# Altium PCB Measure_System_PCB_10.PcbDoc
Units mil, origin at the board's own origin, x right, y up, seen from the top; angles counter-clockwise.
Board outline 6000 x 4000 mil, 2 copper layers (Top Layer, Bottom Layer); 44 components, 29 nets, 115 pads, 0 vias.
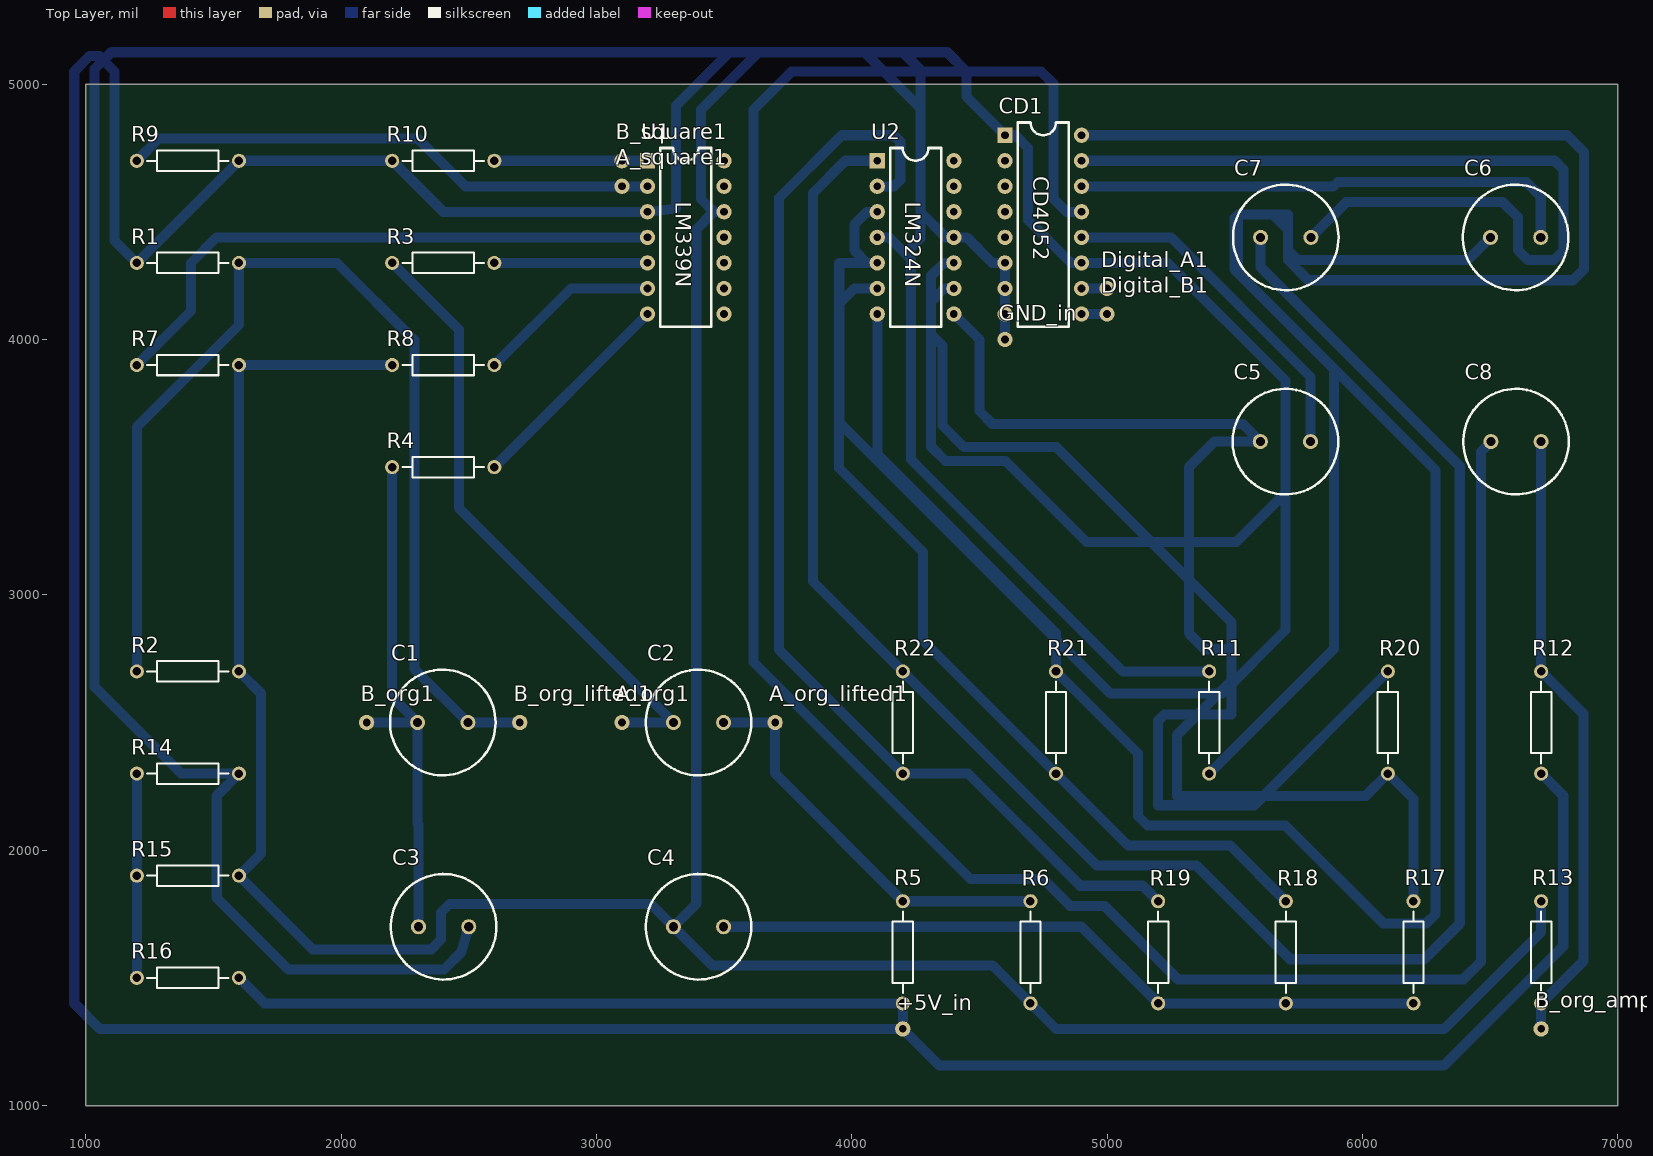
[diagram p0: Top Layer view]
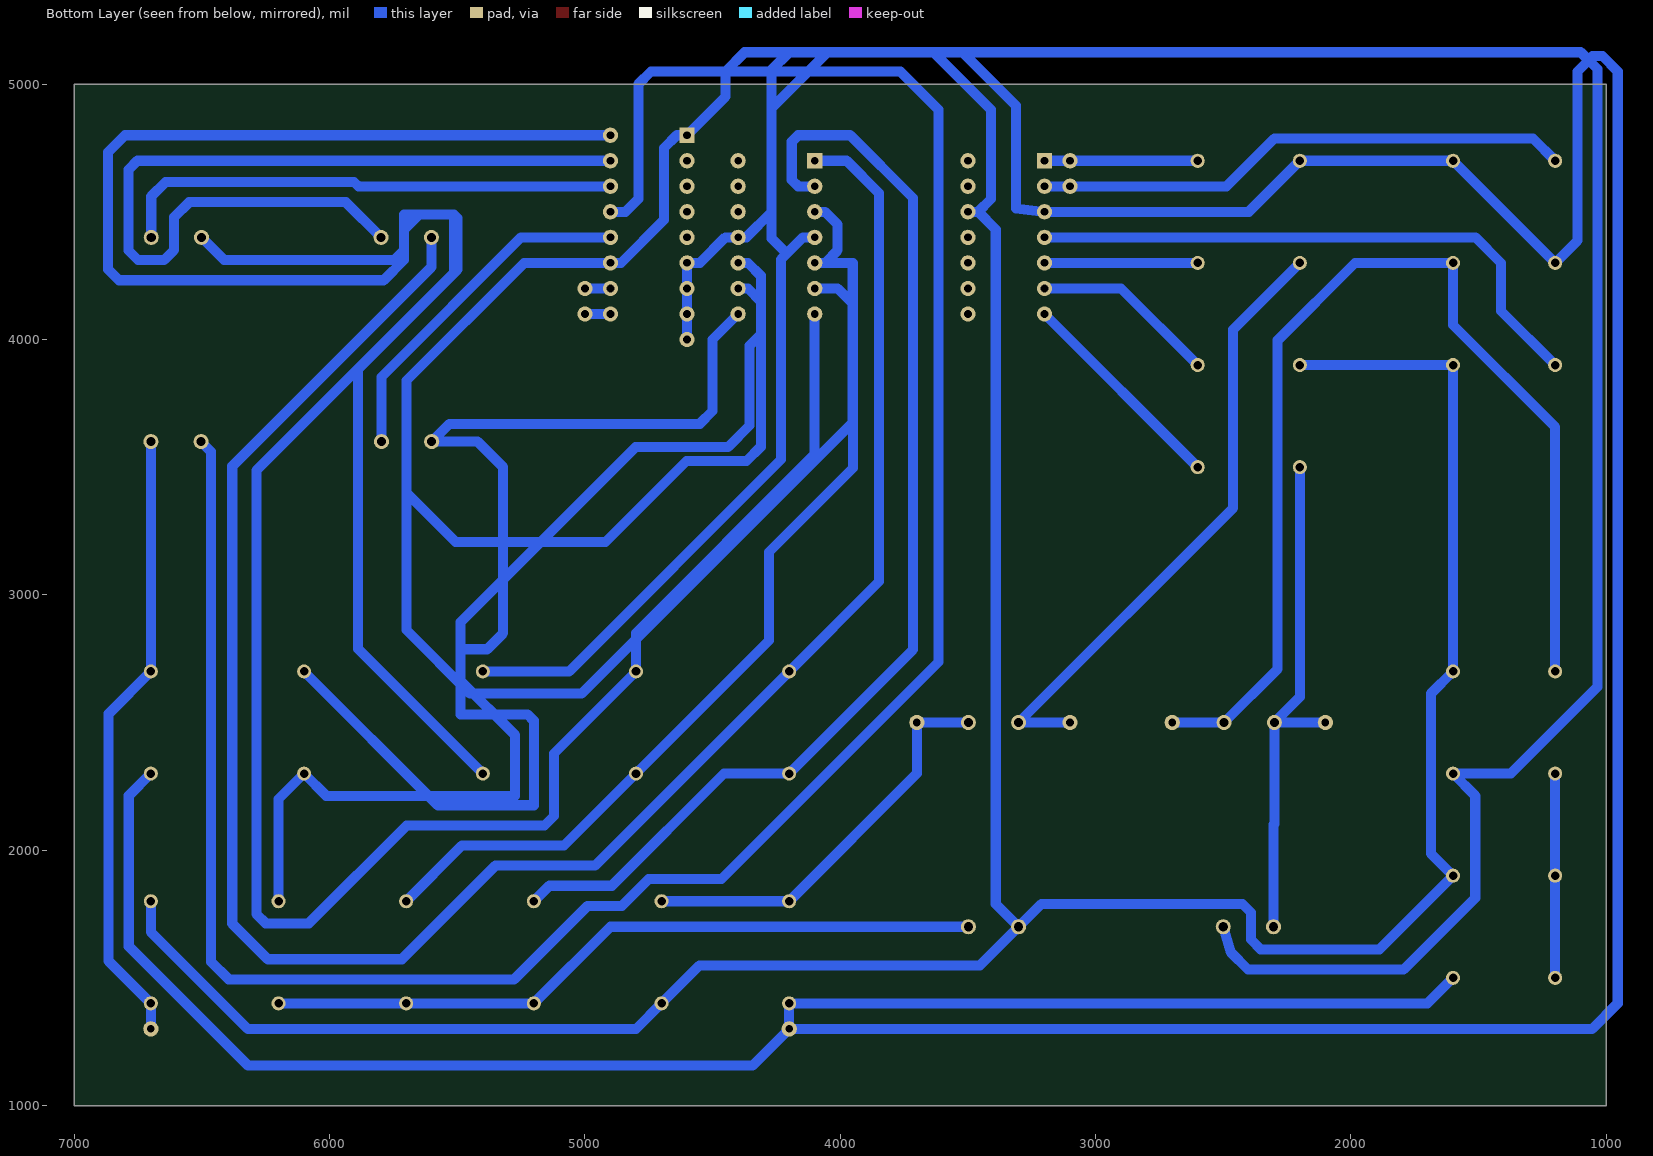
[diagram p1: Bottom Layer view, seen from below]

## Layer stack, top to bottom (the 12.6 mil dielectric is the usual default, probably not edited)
Top Solder: solder mask 0.4, Solder Resist, Dk 3.5
Top Layer: signal copper 1.4
Dielectric 1: dielectric 12.6, FR-4, Dk 4.8
Bottom Layer: signal copper 1.4
Bottom Solder: solder mask 0.4, Solder Resist, Dk 3.5

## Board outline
1000,1000 7000,1000 7000,5000 1000,5000

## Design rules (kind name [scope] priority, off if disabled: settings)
Clearance [All] p1: gap=39.37 ignorepadtopadclearanceinfootprint=FALSE
PolygonConnect [All] p1: connectstyle=Relief reliefconductorwidth=10 reliefentries=4 polygonreliefangle="90 Angle" airgapwidth=10
RoutingLayers [All] p1: top layer_v5=FALSE bottom layer_v5=TRUE
RoutingVias [All] p1: holewidth=28 width=50 viastyle="Through Hole" minholewidth=28 minwidth=50 maxholewidth=28 maxwidth=50
SolderMaskExpansion [All] p1: expansion=4 istentingtop=FALSE
Width [All] p1: maxlimit=3937.01 minlimit=19.68 preferedwidth=39.37 minimp=50.000000 maximp=50.000000 favimp=50.000000
29 further rules are at their usual default settings.

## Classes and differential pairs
component class Part_Square: C1 C2 R1 R2 R3 R4 R5 R6 R7 R8 R9 R10 U1
component class Part_PGA: C3 C4 C5 C6 C7 C8 CD1 R11 R12 R13 R14 R15 R16 R17 R18 R19 R20 R21 R22 U2
component class Measure_System_Main: +5V_in A_org1 A_org_lifted1 A_square1 B_org1 B_org_amped_lifted1 B_org_lifted1 B_square1 Digital_A1 Digital_B1 GND_in

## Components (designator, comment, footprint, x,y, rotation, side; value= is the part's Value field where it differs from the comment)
+5V_in "Hole" Hole 4200,1300 r90 top
A_org1 "Hole" Hole 3100,2500 r90 top
A_org_lifted1 "Hole" Hole 3700,2500 r90 top
A_square1 "Hole" Hole 3100,4600 r90 top
B_org1 "Hole" Hole 2100,2500 r90 top
B_org_amped_lifted1 "Hole" Hole 6700,1300 r90 top
B_org_lifted1 "Hole" Hole 2700,2500 r90 top
B_square1 "Hole" Hole 3100,4700 r90 top
C1 "Cap Pol1" RB5-10.5 2398.43,2500 r0 top value=10u
C2 "Cap Pol1" RB5-10.5 3400,2500 r0 top value=10u
C3 "Cap Pol1" RB5-10.5 2401.57,1700 r0 top value=10u
C4 "Cap Pol1" RB5-10.5 3400,1700 r0 top value=10u
C5 "Cap Pol1" RB5-10.5 5698.43,3600 r0 top value=10u
C6 "Cap Pol1" RB5-10.5 6600,4400 r0 top value=10u
C7 "Cap Pol1" RB5-10.5 5700,4400 r0 top value=10u
C8 "Cap Pol1" RB5-10.5 6601.57,3600 r0 top value=10u
CD1 "CD4052" CD4052 4600,4800 r0 top
Digital_A1 "Hole" Hole 5000,4200 r90 top
Digital_B1 "Hole" Hole 5000,4100 r90 top
GND_in "Hole" Hole 4600,4000 r90 top
R1 "Res2" AXIAL-0.4 1400,4300 r180 top value=100k
R2 "Res2" AXIAL-0.4 1400,2700 r180 top value=100k
R3 "Res2" AXIAL-0.4 2400,4300 r180 top value=1k
R4 "Res2" AXIAL-0.4 2400,3500 r180 top value=1k
R5 "Res2" AXIAL-0.4 4200,1600 r270 top value=100k
R6 "Res2" AXIAL-0.4 4700,1600 r90 top value=100k
R7 "Res2" AXIAL-0.4 1400,3900 r180 top value=10k
R8 "Res2" AXIAL-0.4 2400,3900 r180 top value=10k
R9 "Res2" AXIAL-0.4 1400,4700 r180 top value=10k
R10 "Res2" AXIAL-0.4 2400,4700 r180 top value=10k
R11 "Res2" AXIAL-0.4 5400,2500 r90 top value=200
R12 "Res2" AXIAL-0.4 6700,2500 r270 top value=100k
R13 "Res2" AXIAL-0.4 6700,1600 r270 top value=100k
R14 "Res2" AXIAL-0.4 1400,2300 r0 top value=100k
R15 "Res2" AXIAL-0.4 1400,1900 r180 top value=100k
R16 "Res2" AXIAL-0.4 1400,1500 r180 top value=100k
R17 "Res2" AXIAL-0.4 6200,1600 r90 top value=50k
R18 "Res2" AXIAL-0.4 5700,1600 r90 top value=24k
R19 "Res2" AXIAL-0.4 5200,1600 r90 top value=12k
R20 "Res2" AXIAL-0.4 6100,2500 r90 top value=100k
R21 "Res2" AXIAL-0.4 4800,2500 r90 top value=100k
R22 "Res2" AXIAL-0.4 4200,2500 r90 top value=100k
U1 "LM339N" LM339N 3200,4700 r0 top
U2 "LM324N" LM324N 4100,4700 r0 top

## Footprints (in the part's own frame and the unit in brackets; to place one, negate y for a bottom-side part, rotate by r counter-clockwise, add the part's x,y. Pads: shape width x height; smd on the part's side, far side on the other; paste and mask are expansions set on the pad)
AXIAL-0.4 [mm] "Axial Device, Thru-Hole; 2 Leads; 0.4 in Pin Spacing"
  round 1.4 hole 0.85: 1(-5.08,0) 2(5.08,0)
  silkscreen extent -4.06,-1.02 4.06,1.02
CD4052 [mil]
  rect 60x60 hole 30: 1(0,0)
  round 60 hole 30 mask+4: 2(0,-100) 3(0,-200) 4(0,-300) 5(0,-400) 6(0,-500) 7(0,-600) 8(0,-700) 9(300,-700) 10(300,-600) 11(300,-500) 12(300,-400) 13(300,-300) 14(300,-200) 15(300,-100) 16(300,0)
  silkscreen extent 50,-750 250,50
Hole [mil]
  round 60 hole 30 mask+4: 1(0,0)
LM324N [mil]
  rect 60x60 hole 30: 1(0,0)
  round 60 hole 30 mask+4: 2(0,-100) 3(0,-200) 4(0,-300) 5(0,-400) 6(0,-500) 7(0,-600) 8(300,-600) 9(300,-500) 10(300,-400) 11(300,-300) 12(300,-200) 13(300,-100) 14(300,0)
  silkscreen extent 50,-650 250,50
LM339N [mil]
  rect 60x60 hole 30: 1(0,0)
  round 60 hole 30 mask+4: 2(0,-100) 3(0,-200) 4(0,-300) 5(0,-400) 6(0,-500) 7(0,-600) 8(300,-600) 9(300,-500) 10(300,-400) 11(300,-300) 12(300,-200) 13(300,-100) 14(300,0)
  silkscreen extent 50,-650 250,50
RB5-10.5 [mm] "Capacitor (Radial); 2 Leads"
  round 1.5 hole 0.9: 1(-2.5,0) 2(2.5,0)
  silkscreen extent -5.25,-5.25 5.25,5.25

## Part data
C1 C2 C3 C4 C5 C6 C7 C8: "Polarized Capacitor (Radial)"
R1 R2 R3 R4 R5 R6 R7 R8 R9 R10 R11 R12 R13 R14 R15 R16 R17 R18 R19 R20 R21 R22: "Resistor"

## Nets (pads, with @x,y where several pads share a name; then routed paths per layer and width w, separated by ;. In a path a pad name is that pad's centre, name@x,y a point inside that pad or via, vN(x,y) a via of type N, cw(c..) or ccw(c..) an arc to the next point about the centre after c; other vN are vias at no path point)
+5: +5V_in.1 R1.2 R5.2 R9.1 R10.2 R11.2 R12.2 R16.1 U1.3 U2.4 | length 21267.8
  Bottom Layer w39.37: R16.1 1700,1400 R5.2 +5V_in.1 ; U2.4 4103.76,4400 4146,4400 4209.38,4336.62 ; R11.2 5061.82,2700 4232,3529.82 4232,4314 4209.38,4336.62 ; R12.2 6786.62,2213.38 6786.62,1623.62 6319,1156 4344,1156 +5V_in.1 ; +5V_in.1 1055,1300 955,1400 955,5050 1015,5110 1053,5110 1113,5050 1113,4387 R1.2 R9.1 R10.2 2400,4500 U1.3 3312,4513 3312,4916 3521,5125 4200,5125 4269,5056 4269,4396.24 4209.38,4336.62
B_org: B_org1.1 C1.1 C3.1 R4.2 | length 2042.7
  Bottom Layer w39.37: B_org1.1 C1.1 ; R4.2 2200,2600 C1.1 ; C3.1 2303.15,2100 2300,2103.15 C1.1
B_org_amp_1: C3.2 CD1.1 CD1.11 R14.2 U2.3 U2.5 U2.10 | length 17680.3
  Bottom Layer w39.37: C3.2 2470.48,1600 2403.15,1532.67 1793.33,1532.67 1513,1813 1513,2213 R14.2 1374,2300 1034,2640 1034,5059 1100,5125 4374,5125 4449,5050 4449,4951 CD1.1 4640,4800 4690,4750 4690,4469 4859,4300 CD1.11 5238,4300 ; U2.5 4060,4300 ; U2.3 4060,4500 4010,4450 4010,4350 4060,4300 ; U2.10 4360.94,4300 4310.94,4250 4310.94,3580 4366.94,3524 4602,3524 4919,3207 5506,3207 5699,3400 ; 4060,4300 3951,4300 3951,3675 5013,2613 5450,2613 5699,2862 5699,3400 ; 5238,4300 5238.64,4300 5699,3839.64 5699,3839 ; 5238,4300 5699,3839 ; 5699,3400 5699,3839
B_org_amp_2.5: C5.2 CD1.12 | length 1376.5
  Bottom Layer w39.37: CD1.12 5250,4400 5796.85,3853.15 C5.2
B_org_amp_5: C6.2 CD1.14 | length 1989.5
  Bottom Layer w39.37: CD1.14 5887,4600 5904.03,4617.03 6642.01,4617.03 6698.43,4560.62 C6.2
B_org_amp_10: C7.2 CD1.15 | length 3450.6
  Bottom Layer w39.37: CD1.15 6753,4700 6788,4665 6788,4349 6750,4311 6648,4311 6609,4350 6609,4479 6550,4538 5936.43,4538 C7.2
B_org_amped: C8.1 CD1.13 | length 9447.1
  Bottom Layer w39.37: CD1.13 4841,4500 4791,4550 4791,5000 4741,5050 3765,5050 3615,4900 3615,2737 4465.38,1886.62 4750.38,1886.62 4855.14,1781.86 4989.14,1781.86 5276.91,1494.09 6395.09,1494.09 6464,1563 6464,3560.85 C8.1
Digital_A: CD1.10 Digital_A1.1 | length 100
  Bottom Layer w39.37: CD1.10 Digital_A1.1
Digital_B: CD1.9 Digital_B1.1 | length 100
  Bottom Layer w39.37: CD1.9 Digital_B1.1
GND: C4.1 CD1.6 CD1.7 CD1.8 GND_in.1 R2.1 R6.1 R7.1 R8.2 R13.1 R15.1 U1.12 U2.11 | length 13996.9
  Bottom Layer w39.37: R8.2 R7.1 R2.1 1687,2613 1687,1987 R15.1 1888.58,1611.42 2353.15,1611.42 2391.73,1650 2391.73,1755.73 2425,1789 3212.57,1789 C4.1 ; U1.12 3460,4500 ; GND_in.1 CD1.8 CD1.7 CD1.6 4550,4300 4450,4400 U2.11 4368,4400 4269,4499 4269,4906 4050,5125 3635,5125 3410,4900 3410,4550 3460,4500 ; R13.1 6700,1679.68 6320.32,1300 4800,1300 R6.1 4552,1548 3453.57,1548 C4.1 ; C4.1 3391,1789.43 3391,4431 3460,4500
NetA_org1_1: A_org1.1 C2.1 R3.2 | length 2457.9
  Bottom Layer w39.37: R3.2 2461,4039 2461,3340.57 C2.1 A_org1.1
NetA_org_lifted1_1: A_org_lifted1.1 C2.2 R5.1 R6.2 | length 1608.7
  Bottom Layer w39.37: C2.2 A_org_lifted1.1 3700,2300 R5.1 R6.2
NetA_square1_1: A_square1.1 R9.2 U1.2 | length 2113.5
  Bottom Layer w39.37: R9.2 1287,4787 2300,4787 2487,4600 A_square1.1 U1.2
NetB_org_amped_lifted1_1: B_org_amped_lifted1.1 C8.2 R12.1 R13.2 | length 2437
  Bottom Layer w39.37: B_org_amped_lifted1.1 R13.2 6865.36,1565.36 6865.36,2534.64 R12.1 C8.2
NetB_org_lifted1_1: B_org_lifted1.1 C1.2 R1.1 R2.2 | length 4365.3
  Bottom Layer w39.37: R2.2 1200,3657 1600,4057 R1.1 1984,4300 2287,3997 2287,2709.85 C1.2 B_org_lifted1.1
NetB_square1_1: B_square1.1 R10.1 U1.1 | length 600
  Bottom Layer w39.37: R10.1 B_square1.1 U1.1
NetC4_2: C4.2 R17.1 R18.1 R19.1 | length 2825.8
  Bottom Layer w39.37: C4.2 4900,1700 R19.1 R18.1 R17.1
NetC5_1: C5.1 R20.2 U2.8 | length 4736.2
  Bottom Layer w39.37: U2.8 4500,4000 4500,3719.74 4550,3669.74 5530.26,3669.74 C5.1 5420,3600 5320,3500 5320,2850 5383,2787 5487,2787 5487,2532 5225,2532 5200,2507 5200,2176 5576,2176 R20.2
NetC6_1: C6.1 R21.2 U2.7 | length 7951
  Bottom Layer w39.37: U2.7 4100,3550.47 4800,2850.47 R21.2 5121.26,2378.74 5121.26,2134.26 5158.68,2096.83 5698.17,2096.83 6081.62,1713.38 6250.38,1713.38 6287,1750 6287,3486.64 5512,4261.64 5512,4489 5650,4489 5709,4430 5709,4350 5748,4311 6412.57,4311 C6.1
NetC7_1: C7.1 R22.2 U2.1 | length 8040
  Bottom Layer w39.37: U2.1 3975,4700 3848.16,4573.16 3848.16,3051.84 R22.2 4960.65,1939.35 5350.81,1939.35 5717.33,1572.83 6241.91,1572.83 6381.3,1712.22 6381.3,3503.7 5601.57,4283.43 C7.1
NetCD1_16: CD1.16 R11.1 | length 6593.7
  Bottom Layer w39.37: CD1.16 6801,4800 6867,4734 6867,4274 6825,4232 5788,4232 5709,4311 5709,4489 5513,4489 5500,4476 5500,4273.64 5888,3885.64 5888,2788 R11.1
NetR3_1: R3.1 U1.5 | length 600
  Bottom Layer w39.37: R3.1 U1.5
NetR4_1: R4.1 U1.7 | length 848.5
  Bottom Layer w39.37: R4.1 U1.7
NetR7_2: R7.2 U1.4 | length 2317.2
  Bottom Layer w39.37: R7.2 1412,4112 1412,4300 1512,4400 U1.4
NetR8_1: R8.1 U1.6 | length 724.3
  Bottom Layer w39.37: R8.1 2900,4200 U1.6
NetR14_1: R14.1 R15.2 R16.2 | length 800
  Bottom Layer w39.37: R16.2 R15.2 R14.1
NetR17_2: R17.2 R20.1 U2.9 | length 4239.1
  Bottom Layer w39.37: U2.9 4360.94,4200 4310.94,4150 4310.94,4020 4355,3975.94 4355,3663 4439,3579 4801,3579 5487,2893 5487,2664 5273,2450 5273,2213 6013,2213 R20.1 6200,2200 R17.2
NetR18_2: R18.2 R21.1 U2.6 | length 3474
  Bottom Layer w39.37: U2.6 4010,4200 3950,4140 3950,3497 4279,3168 4279,2821 R21.1 5081.91,2018.09 5481.91,2018.09 R18.2
NetR19_2: R19.2 R22.1 U2.2 | length 4499.8
  Bottom Layer w39.37: U2.2 4165,4600 4190,4625 4190,4775 4165,4800 3961,4800 3714.77,4553.77 3714.77,2785.23 R22.1 4455.53,2300 4894.92,1860.61 5139.39,1860.61 R19.2
pads on no net: CD1.2 CD1.3 CD1.4 CD1.5 U1.8 U1.9 U1.10 U1.11 U1.13 U1.14 U2.12 U2.13 U2.14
